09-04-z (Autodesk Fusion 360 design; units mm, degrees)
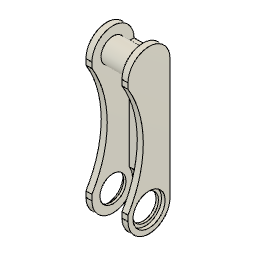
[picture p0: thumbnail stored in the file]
sketch "スケッチ1" plane through (0, 0, 0) normal (1, 0, 0) x axis (0, 0, -1)
  circle C1 centre (0, 40) radius 4
  point P1 (0, 0)
  point P2 (0, 40)
  vertical P1 P2
  dimension "d1" diameter C1 = 8
  dimension "d29" distance P1 P2 = 40
extrude "押し出し1" new body sketch "スケッチ1" + "スケッチ5" profile of S1:C1 distance 10
sketch "スケッチ2" plane through (5, 0, 0) normal (1, 0, 0) x axis (0, 0, -1)
  line L1 (-7, 0) -> (-7, 40)
  line L2 (7, 40) -> (7, 0)
  line L3 (0, 0) -> (0, 40)
  circle C1 centre (0, 40) radius 4
  arc A1 centre (0, 0) radius 7 clockwise from (7, 0) to (-7, 0)
  arc A2 centre (0, 40) radius 7 clockwise from (-7, 40) to (7, 40)
  point P7 (0, 40)
  point P9 (0, 40)
  point P8 (0, 0)
  tangent L1 A1
  tangent A1 L2
  parallel L1 L2
  tangent L2 A2
  tangent L1 A2
  vertical L3
  coincident P7 P9
  concentric C1 A2
  dimension "d4" radius A2 = 7
  dimension "d5" distance P7 P8 = 40
extrude "押し出し2" add sketch "スケッチ2" profile of C1 L1 A1 L2 A2 along normal blind 2
mirror "ミラー" sketch "スケッチ5" mirrorStitchTolerance 0.1
sketch "スケッチ3" plane through (0, 0, 0) normal (1, 0, 0) x axis (0, 0, -1)
  line L1 (7, 40) -> (5.4, 40)
  line L2 (7, 0) -> (7, 40)
  line L3 (5.4, 0) -> (7, 0)
  line L4 (5.4, 40) -> (5.4, 0)
  point P3 (7, 40)
  point P6 (7, 40)
  point P4 (7, 0)
  point P7 (7, 0)
  horizontal L1
  vertical L2
  horizontal L3
  vertical L4
  coincident P3 P6
  coincident P4 P7
  dimension "d10" distance L2 L4 = 1.6
extrude "押し出し3" add sketch "スケッチ3" distance 10
sketch "スケッチ4" plane through (0, 0, 0) normal (1, 0, 0) x axis (0, 0, -1)
  circle C1 centre (-36.9324, 20) radius 35
  arc A1 centre (0, 40) radius 7 clockwise from (-7, 40) to (7, 40)
  arc A2 centre (0, 0) radius 7 clockwise from (7, 0) to (-7, 0)
  tangent C1 A1
  tangent C1 A2
  dimension "d13" diameter C1 = 70
extrude "押し出し4" cut sketch "スケッチ4" profile of C1 no distance stored
sketch "スケッチ5" plane through (0, 0, 0) normal (1, 0, 0) x axis (0, 0, -1)
  circle C1 centre (0, 0) radius 6.5
  arc A1 centre (0, 0) radius 7 clockwise from (7, 0) to (-7, 0)
  concentric C1 A1
  dimension "d15" diameter C1 = 13
extrude "押し出し5" cut sketch "スケッチ5" profile of C1 distance 10
chamfer "面取り" distance 0.2
hole "穴1" HoleDepth 2 HoleDiameter 8.7 TipAngle 118 CBDepth 1.2 CBDiameter 10.7
hole "穴2" HoleDepth 2 HoleDiameter 8.7 TipAngle 118 CBDepth 1.2 CBDiameter 10.7
joint_origin "JointOrigin3" OffsetX 0 OffsetY 0 OffsetZ 0 AngleZ 180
